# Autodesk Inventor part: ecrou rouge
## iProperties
Shininess: 20.0
Length Units: 11269
Angle Units: 11279
Time Units: 11290
Mass Units: 11283
Length Display Precision: 3
Angle Display Precision: 2
Created: 2002-01
Part Number: ecrou rouge
Material: Par défaut
Document SubType Name: Modélisation
Designer: Chris...
Density: 0.0
Volumn: 0.0
Area: 0.0
PropertySet Name: Model Information
Control State: 0
Master: False
Checked Out: False
Author: Chris...
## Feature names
1. Hélicoïde1
2. Réseau circulaire1 [Circular Pattern]
3. Extrusion3
4. Balayage1
5. Réseau rectangulaire1 [Rectangular Pattern]
6. Corps dérivé1 [Tagging]
